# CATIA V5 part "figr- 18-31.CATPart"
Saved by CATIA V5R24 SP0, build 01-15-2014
Part number: Part1
Bounding box of the stored display mesh (mm): x -37.5 to 37.5, y -50 to 50, z 0 to 59.069
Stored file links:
  D:\KAVITA\CATIA V5-6R2014 Project_ Kavita\CATIA V5-6R2014_partfiles\Partfiles\c17_caia_v6-6r2014_prt\figure- 17-31.CATPart
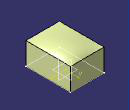
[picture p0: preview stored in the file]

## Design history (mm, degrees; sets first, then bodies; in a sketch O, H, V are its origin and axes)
Set1
  Sketch1 on xy-plane, origin (0, 0, 0), H (1, 0, 0), V (0, 1, 0)
    line L1 (37.5, 50) -> (37.5, -50)
    line L2 (37.5, -50) -> (-37.5, -50)
    line L3 (-37.5, -50) -> (-37.5, 50)
    line L4 (-37.5, 50) -> (37.5, 50)
    length L4 = 75
    length L1 = 100
    vertical: L1 V, L3 V
    horizontal: L2 H, L4 H
    equidistance: L1 L3 O, L2 L4 O
  Extrude1: Element1 Sketch1, Lim1 50, Lim2 0
  DatumSurface1
Body1 (main body)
